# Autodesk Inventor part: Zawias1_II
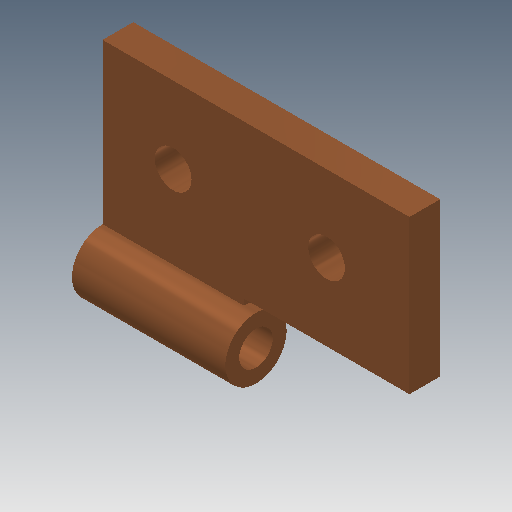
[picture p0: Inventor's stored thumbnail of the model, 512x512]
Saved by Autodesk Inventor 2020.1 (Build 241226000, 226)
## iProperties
Created: 2005-09
Part Number: Zawias1_II
Document SubType Name: Modeling
Designer: F.Stasiak
Density: 1 g/cm^3
Mass: 7.57519 g
Surface Area: 45.3842 cm^2
Volume: 7.57519 cm^3
Material: Ogólny
Appearance: Miedziany (stary/polerowany)
Manager: www.cadconsulting.pl
Company: Fabian Stasiak CAD Consulting
d0: 50,000 mm
d2: 23,000 mm
d4: 5,000 mm
d5: 0,00 deg
d7: 0,00 deg
d16: 6,000 mm
d24: 2,000 mm
d25: 0,00 deg
d26: 5,500 mm
d34: 25,000 mm
d35: 6,000 mm
Author: F.Stasiak
Subject: Zbiór ćwiczeń. Autodesk Inventor 2020. Kurs podstawowy
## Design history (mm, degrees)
sketch "Szkic1"
  geometry: L1 (-2, -31)-(-25, -31); L2 (-25, -31)-(-25, 0); L3 (-25, 0)-(25, 0); L4 (25, 0)-(25, -25); L5 (25, -25)-(-2, -25); L6 (-2, -25)-(-2, -31); 2 further points
  constraints: 12 end point, 4 parallel, 1 coincident, 1 horizontal, 1 midpoint, 1 perpendicular
  dimensions: "d0" = 50 distance of L2.end L3.end; "d2" = 23 distance of L1.start L1.end (computed from d0); "d34" = 25 distance of L3.end L4.end; "d35" = 6 distance of L5.end L1.start
extrude "Wyciągnięcie proste1" new body sketch "Szkic1" distance "d4" = 5; taper "d5" = 0 deg
sketch "Szkic2"
  geometry: L1 (-5, 6)-(-5, 0) reference; L2 (0, 6)-(0, 0) reference; C1 r 5 at (-5, 0)
  constraints: 1 centre point, 1 coincident
extrude "Wyciągnięcie proste2" join sketch "Szkic2" stored distance "d6" = 25; taper "d7" = 0 deg
sketch "Szkic4"
  geometry: L1 (25, 0)-(25, -25) reference; L2 (-25, -26)-(-25, 0) reference; L3 (25, -12.5)-(-25, -12.5); L4 (25, -25)-(-2, -25) reference; L5 (-25, -26)-(-2, -26) reference; L6 (11.5, -25)-(11.5, -12.5); L7 (-13.5, -26)-(-13.5, -12.5)
  constraints: 6 end point, 3 midpoint, 3 perpendicular, 3 point on line
hole "Otwór2" sketch "Szkic4" at (11.5, -12.5), (-13.5, -12.5) diameter "d16" = 6; stored, may be unused: countersink angle "d20" = 120 deg, drill point angle "d22" = 118 deg; dims "d17" = 6, "d18" = 8, "d19" = 2, "d21" = 30
sketch "Szkic5"
  geometry: C1 r 5 at (-5, 0); 3 further points
  constraints: 1 centre point, 1 coincident, 2 other
extrude "Wyciągnięcie proste3" join sketch "Szkic5" distance "d24" = 2; taper "d25" = 0 deg
sketch "Szkic6"
  geometry: C1 r 5 at (0, 0) reference
hole "Otwór3" sketch "Szkic6" at (0, 0) diameter "d26" = 5.5; stored, may be unused: countersink angle "d30" = 120 deg, drill point angle "d32" = 118 deg; dims "d27" = 6, "d28" = 8, "d29" = 2, "d31" = 30
node "Bryła1"
node "Korpusy bryłowe"
node "Korpusy powierzchniowe"
